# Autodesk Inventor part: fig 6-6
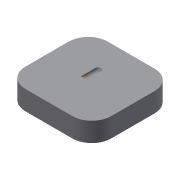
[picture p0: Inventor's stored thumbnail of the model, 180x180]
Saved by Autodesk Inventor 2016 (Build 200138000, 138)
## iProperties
Created: 2004-05
Part Number: fig 6-6
Document SubType Name: Modeling
Designer: CADCIM Technologies
Manufacturer: Standard
Standards Organization: Custom
Density: 1 g/cm^3
Material: Generic
Appearance: Default
Author: CADCIM Technologies
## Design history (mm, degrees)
sketch "Sketch1"
  geometry: L1 (0, 0)-(44.293, 0); L2 (44.293, 0)-(44.293, 42.442); L3 (44.293, 42.442)-(0, 42.442); L4 (0, 42.442)-(0, 0)
  constraints: 8 end point, 2 parallel, 1 horizontal, 1 perpendicular
extrude "Extrusion1" new body sketch "Sketch1" distance "d0" = 10; taper "d1" = 0 deg
fillet "Fillet1" dims "d2" = 10
sketch "Sketch2"
  geometry: 1 further point
sketch "Sketch3"
  geometry: L1 (10, 42.442)-(34.293, 42.442) reference; L2 (0, 10)-(0, 32.442) reference; L3 (34.293, 0)-(10, 0) reference; L4 (44.293, 32.442)-(44.293, 10) reference; A1 r 10 centre (34.293, 32.442) between (44.293, 32.442) and (34.293, 42.442) reference; A2 r 10 centre (10, 32.442) between (10, 42.442) and (0, 32.442) reference; A3 r 10 centre (10, 10) between (0, 10) and (10, 0) reference; A4 r 10 centre (34.293, 10) between (34.293, 0) and (44.293, 10) reference; 1 further point
workpoint "Work Point1"
hole "Hole4" diameter "d33" = 3; stored, may be unused: countersink angle "d37" = 90 deg, drill point angle "d39" = 118 deg; dims "d31" = 10, "d32" = 10, "d34" = 6, "d35" = 4, "d36" = 2, "d38" = 8
body "Solid1"
